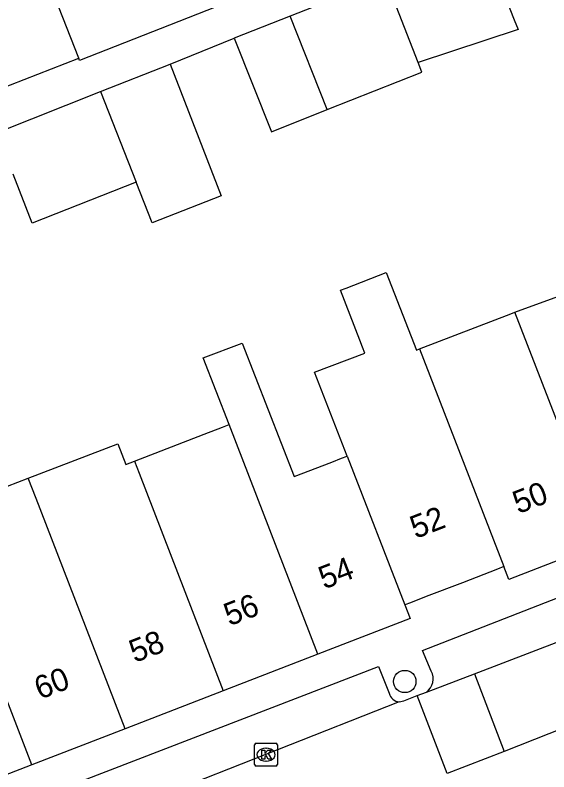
# Model space of a CAD drawing. Extents: x 161696 to 162377, y 380761 to 381673.
# Drawn here: x 161918.18 to 161941.55, y 381149.93 to 381183.08 of the extents above; entities that cross this region are included whole.
import ezdxf

# ---------------------------------------------------------------- set-up
doc = ezdxf.new("R2010")
doc.units = 0
for name, color, linetype in [('IMGEO_Boom', 7, 'Continuous'), ('IMGEO_Erf', 7, 'Continuous'), ('IMGEO_Kolk', 7, 'Continuous'), ('IMGEO_Pand', 7, 'Continuous'), ('IMGEO_Pand_nummerreeks', 7, 'Continuous'), ('IMGEO_Rijbaan_lokaal_open', 7, 'Continuous'), ('IMGEO_Voetpad_open', 7, 'Continuous')]:
    doc.layers.add(name, color=color, linetype=linetype)

msp = doc.modelspace()

# ---------------------------------------------------------------- linework, layer by layer
at = {"layer": 'IMGEO_Boom'}
msp.add_circle((161935.246, 381153.888), 0.489, dxfattribs=at)
at = {"layer": 'IMGEO_Erf'}
msp.add_lwpolyline([(161927.781, 381182.066), (161929.404, 381177.97), (161931.85, 381178.939)], dxfattribs=at)
at = {"layer": 'IMGEO_Kolk'}
for p, q in [((161928.67, 381150.258), (161928.67, 381151.11)), ((161928.745, 381151.184), (161929.597, 381151.184)), ((161929.158, 381150.964), (161929.183, 381150.964)), ((161929.671, 381151.11), (161929.671, 381150.258)), ((161929.181, 381150.404), (161929.156, 381150.404)), ((161929.597, 381150.184), (161928.745, 381150.184))]:
    msp.add_line(p, q, dxfattribs=at)
for points in [[(161928.67, 381150.258), (161928.67, 381151.11)], [(161928.745, 381151.184), (161929.597, 381151.184)], [(161929.671, 381151.11), (161929.671, 381150.258)], [(161928.991, 381150.884), (161929.114, 381150.884), (161929.114, 381150.733), (161929.244, 381150.884), (161929.408, 381150.884), (161929.262, 381150.733), (161929.415, 381150.484), (161929.263, 381150.484), (161929.178, 381150.648), (161929.114, 381150.581), (161929.114, 381150.484), (161928.991, 381150.484), (161928.991, 381150.884)], [(161929.597, 381150.184), (161928.745, 381150.184)]]:
    msp.add_lwpolyline(points, dxfattribs=at)
for centre, start, end in [((161928.747, 381151.108), 91.552, 178.448), ((161928.747, 381151.108), 91.552, 178.448), ((161929.595, 381151.108), 1.552, 88.448), ((161929.595, 381151.108), 1.552, 88.448), ((161928.747, 381150.26), 181.552, 268.448), ((161928.747, 381150.26), 181.552, 268.448), ((161929.595, 381150.26), 271.552, 358.448), ((161929.595, 381150.26), 271.552, 358.448)]:
    msp.add_arc(centre, 0.0765, start, end, dxfattribs=at)
for centre, major_axis, ratio, start_param, end_param in [((161929.157, 381150.684), (-0.387, 0.002), 0.722429, 4.712389, 7.853982), ((161929.182, 381150.684), (-0.39, 0.002), 0.717154, 1.570796, 4.712389)]:
    msp.add_ellipse(centre, major_axis=major_axis, ratio=ratio, start_param=start_param, end_param=end_param, dxfattribs=at)
at = {"layer": 'IMGEO_Pand'}
for points in [[(161920.97, 381181.186), (161919.579, 381184.775), (161926.327, 381187.39), (161926.437, 381187.106)], [(161938.661, 381186.377), (161940.041, 381182.878), (161940.212, 381182.446), (161935.824, 381181.005)], [(161934.396, 381184.687), (161930.233, 381183.038)], [(161935.824, 381181.005), (161934.396, 381184.687)], [(161927.736, 381183.754), (161921.004, 381181.098), (161920.97, 381181.186)], [(161931.85, 381178.939), (161930.233, 381183.038)], [(161921.922, 381179.727), (161924.975, 381180.932)], [(161924.975, 381180.932), (161927.21, 381175.167), (161924.191, 381173.976), (161923.487, 381175.76)], [(161931.85, 381178.939), (161935.991, 381180.581), (161935.824, 381181.005)], [(161917.393, 381177.94), (161921.922, 381179.727)], [(161921.922, 381179.727), (161923.487, 381175.76)], [(161923.487, 381175.76), (161918.93, 381173.963), (161918.1, 381176.11)], [(161932.723, 381163.76), (161932.52, 381164.283), (161931.297, 381167.437), (161933.497, 381168.272), (161933.396, 381168.535), (161933.28, 381168.836), (161932.437, 381171.028), (161932.681, 381171.122), (161934.436, 381171.8), (161935.751, 381168.401), (161935.894, 381168.456)], [(161940.063, 381170.065), (161944.031, 381171.514), (161944.369, 381171.64)], [(161935.894, 381168.456), (161939.885, 381170), (161940.063, 381170.065)], [(161943.975, 381159.97), (161940.063, 381170.065)], [(161927.552, 381165.145), (161926.424, 381168.067), (161928.132, 381168.709), (161930.398, 381162.861), (161932.055, 381163.502), (161932.48, 381163.666), (161932.723, 381163.76)], [(161935.894, 381168.456), (161939.588, 381158.922)], [(161923.411, 381163.543), (161926.461, 381164.723), (161927.263, 381165.033), (161927.552, 381165.145)], [(161931.439, 381155.081), (161927.552, 381165.145)], [(161918.758, 381162.789), (161922.678, 381164.303), (161923.029, 381163.395), (161923.411, 381163.543)], [(161923.411, 381163.543), (161923.618, 381163.009), (161927.299, 381153.48)], [(161932.723, 381163.76), (161935.249, 381157.244)], [(161914.674, 381161.212), (161918.758, 381162.789)], [(161922.997, 381151.816), (161919.103, 381161.897), (161918.758, 381162.789)], [(161918.913, 381150.237), (161916.157, 381157.372), (161914.674, 381161.212)], [(161943.975, 381159.97), (161939.807, 381158.358), (161939.588, 381158.922)], [(161939.588, 381158.922), (161939.308, 381158.814), (161937.765, 381158.217), (161936.185, 381157.606), (161935.495, 381157.339), (161935.249, 381157.244)], [(161935.249, 381157.244), (161935.481, 381156.644), (161931.439, 381155.081)], [(161931.439, 381155.081), (161927.299, 381153.48)], [(161927.299, 381153.48), (161922.997, 381151.816)], [(161922.997, 381151.816), (161918.913, 381150.237)], [(161918.913, 381150.237), (161914.726, 381148.618)]]:
    msp.add_lwpolyline(points, dxfattribs=at)
at = {"layer": 'IMGEO_Rijbaan_lokaal_open'}
for points in [[(161938.293, 381154.231), (161950.652, 381158.97), (161962.069, 381163.406)], [(161936.189, 381153.424), (161938.293, 381154.231)], [(161938.293, 381154.231), (161939.598, 381150.828)], [(161948.078, 381154.173), (161941.553, 381151.59)], [(161934.999, 381152.99), (161935.204, 381153.046), (161935.791, 381153.271)], [(161935.791, 381153.271), (161936.189, 381153.424)], [(161937.101, 381149.855), (161935.791, 381153.271)], [(161934.999, 381152.99), (161924.339, 381148.789), (161914.335, 381144.949)], [(161941.553, 381151.59), (161939.598, 381150.828)], [(161939.598, 381150.828), (161937.101, 381149.855)]]:
    msp.add_lwpolyline(points, dxfattribs=at)
at = {"layer": 'IMGEO_Voetpad_open'}
for points in [[(161930.233, 381183.038), (161927.781, 381182.066)], [(161924.975, 381180.932), (161927.781, 381182.066)], [(161916.769, 381179.551), (161920.97, 381181.186)], [(161936.401, 381154.343), (161936.022, 381155.245), (161961.935, 381165.359)], [(161914.489, 381145.735), (161914.06, 381146.828), (161934.09, 381154.552), (161934.558, 381153.37)]]:
    msp.add_lwpolyline(points, dxfattribs=at)
for centre, radius, start, end in [((161935.783, 381154.002), 0.706, 305.0985, 28.9213), ((161935.052, 381153.498), 0.51, 194.4865, 264.012)]:
    msp.add_arc(centre, radius, start, end, dxfattribs=at)

# ---------------------------------------------------------------- texts
at = {"layer": 'IMGEO_Pand_nummerreeks'}
for s, rotation, p in [('50', 21.1421, (161940.212, 381161.216)), ('52', 21.1479, (161935.718, 381160.128)), ('54', 21.2109, (161931.714, 381157.914)), ('56', 21.2109, (161927.565, 381156.304)), ('58', 21.2109, (161923.419, 381154.696)), ('60', 21.2131, (161919.27, 381153.085))]:
    msp.add_text(s, height=1, rotation=rotation, dxfattribs=at).set_placement(p)

doc.saveas('drawing.dxf')
